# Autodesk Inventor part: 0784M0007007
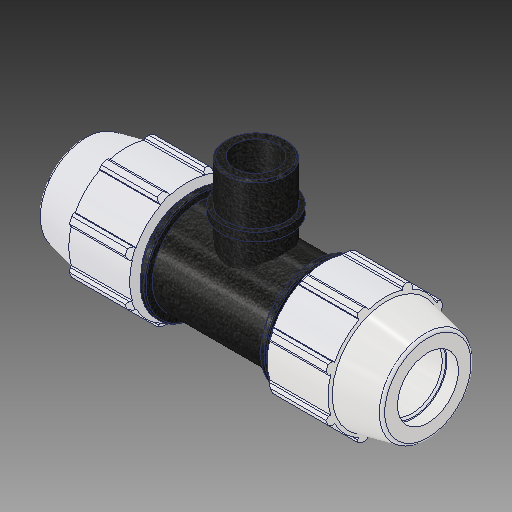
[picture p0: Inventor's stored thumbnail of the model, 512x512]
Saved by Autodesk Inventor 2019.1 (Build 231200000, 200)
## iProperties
Created: 2017-02
Part Number: 0784M0007007
Material: PVC-Piping
Description: PLASSON TEE WITH THREADED MALE OFFTAKE 3/4'' - 3/4''M - 3/4''
Document SubType Name: Modeling
Designer: KIM
Mass: 92.6774 g
Surface Area: 199.44 cm^2
Volume: 66.1981 cm^3
Density: 1.4 g/cm^3
Appearance: PTFE
Author: Кирилл
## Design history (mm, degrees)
derived "0784M0.ipt"
feature "Solid1::0784M0.ipt"
feature "Solid2::0784M0.ipt"
tag "TaggingFeature1"
body "Solid1"
body "Solid2"
other parameters: "d2" = 26.6, "d4" = 6.25475, "d5" = 18.01368, "d7" = 54.102, "d11" = 2.5019, "d13" = 120 deg, "d14" = 39.9, "d15" = 12 deg, "d16" = 47.06874, "d18" = 1.33, "d19" = 35 deg, "d20" = 17.5 deg, "d21" = 50.31486, "d23" = 0, "d25" = 360 deg, "d27" = 1.08204, "d33" = 0.532, "d42" = 27.02052, "d43" = 1.62306, "d46" = 0.798, "d68" = 2.5019, "d72" = 50.038, "d73" = 26.441, "d74" = 18.034, "d75" = 30.40715, "d76" = 18.5087, "d77" = 21.6408, "d80" = 0.79323, "d91" = 40.5765, "d93" = 60.96, "d95" = 23.94, "d99" = 150.114, "d101" = 0, "d103" = 0, "d105" = 0, "d_" = 26.6, "E_" = 54.102, "A_" = 50.038, "l_" = 60.96, "l_2" = 18.034, "H_" = 150.114, "G_" = 26.441
